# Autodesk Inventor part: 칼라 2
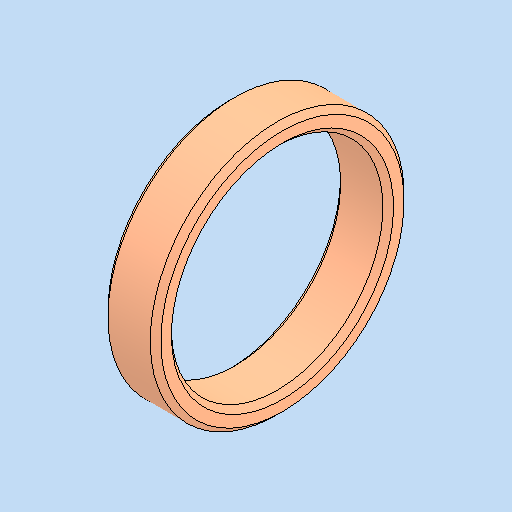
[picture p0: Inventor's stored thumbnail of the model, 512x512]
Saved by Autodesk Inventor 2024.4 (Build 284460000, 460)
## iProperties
Created: 2025-11
Part Number: 칼라 2
Material: 강철, 연강
Document SubType Name: Modeling
Designer: home
Density: 7.85 g/cm^3
Appearance: 기본값
Author: jhkim
Sending System: Autodesk Inventor 2026
Preprocessor: ST-DEVELOPER v20.1
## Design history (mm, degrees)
feature "솔리드1"
node "솔리드2"
